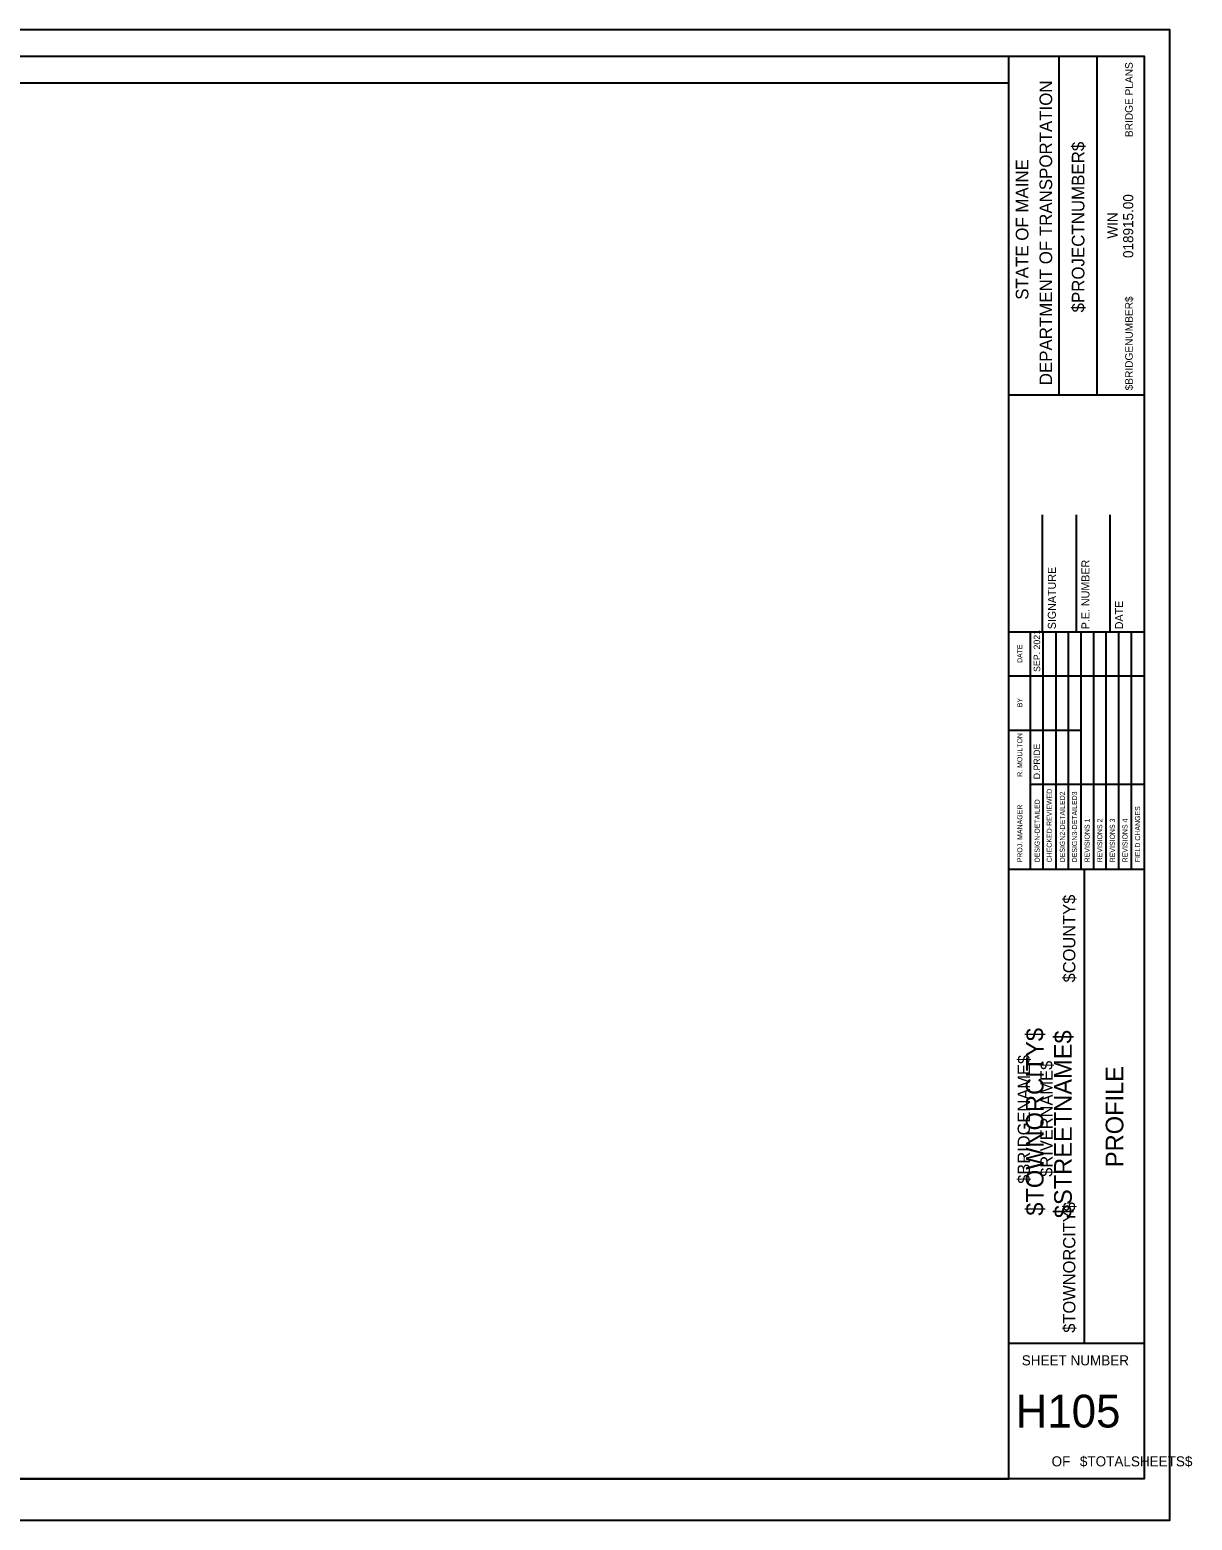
# Model space of a CAD drawing. Extents: x 36591 to 37449, y 9985 to 10535.
# Drawn here: x 37020 to 37449, y 9985 to 10535 of the extents above; entities that cross this region are included whole.
import ezdxf

# ---------------------------------------------------------------- set-up
doc = ezdxf.new("R2010")
doc.units = 0
for name, color, linetype in [('BORDER', 7, 'Continuous'), ('BRIDGE_TITLE', 7, 'Continuous'), ('CLIPS', 7, 'Continuous'), ('HIGHWAY_TITLE', 7, 'Continuous'), ('PLOT BOUNDARY', 7, 'Continuous')]:
    doc.layers.add(name, color=color, linetype=linetype)

msp = doc.modelspace()

# ---------------------------------------------------------------- linework, layer by layer
at = {"layer": 'BORDER'}
for p, q in [((37381.12, 10000), (37381.12, 10525)), ((37399.77, 10399.99), (37399.77, 10524.99)), ((37413.74, 10399.99), (37413.74, 10524.99)), ((37381.13, 10399.97), (37431.12, 10399.97)), ((37393.62, 10312.51), (37393.62, 10355.75)), ((37406.12, 10312.51), (37406.12, 10355.75)), ((37418.62, 10312.51), (37418.62, 10355.75)), ((37381.12, 10312.51), (37431.12, 10312.51)), ((37381.12, 10225.01), (37431.12, 10225.01)), ((37409.08, 10050.01), (37409.08, 10225.01)), ((37381.12, 10050.01), (37431.12, 10050.01))]:
    msp.add_line(p, q, dxfattribs=at)
msp.add_lwpolyline([(36631.12, 10525), (37431.12, 10525), (37431.12, 10000), (36631.12, 10000)], close=True, dxfattribs=at)
for points in [[(37389.2, 10296.26), (37389.2, 10312.51)], [(37393.86, 10225.03), (37393.86, 10312.51)], [(37398.52, 10312.51), (37398.52, 10225.03)], [(37403.18, 10225.03), (37403.18, 10312.51)], [(37407.84, 10225.03), (37407.84, 10312.51)], [(37412.5, 10225.03), (37412.5, 10312.51)], [(37417.15, 10225.03), (37417.15, 10312.51)], [(37421.81, 10225.03), (37421.81, 10312.51)], [(37426.47, 10225.03), (37426.47, 10312.51)], [(37389.2, 10225.03), (37389.2, 10308.98)], [(37381.12, 10296.26), (37431.12, 10296.26)], [(37381.12, 10276.26), (37389.2, 10276.26)], [(37389.2, 10276.26), (37407.83, 10276.26)], [(37389.2, 10256.26), (37431.12, 10256.26)]]:
    msp.add_lwpolyline(points, dxfattribs=at)
at = {"layer": 'CLIPS'}
msp.add_lwpolyline([(36631.12, 10000), (37381.12, 10000), (37381.12, 10515), (36631.12, 10515)], close=True, dxfattribs=at)
at = {"layer": 'PLOT BOUNDARY'}
msp.add_lwpolyline([(36590.66, 9984.7), (37440.66, 9984.7), (37440.66, 10534.7), (36590.66, 10534.7)], close=True, dxfattribs=at)

# ---------------------------------------------------------------- texts
at = {"layer": 'BORDER'}
for s, height, rotation, p in [('DEPARTMENT OF TRANSPORTATION', 4.6588, 90, (37397.16, 10403.53)), ('$PROJECTNUMBER$', 4.6588, 90, (37409.08, 10430.4)), ('STATE OF MAINE', 4.6588, 90, (37388.4, 10435.06)), ('018915.00', 3.726, 90, (37427.1, 10450.49)), ('WIN', 3.726, 90, (37421.31, 10457.65)), ('SIGNATURE', 2.953, 90, (37398.53, 10313.48)), ('P.E. NUMBER', 2.9528, 90, (37410.93, 10313.48)), ('DATE', 2.953, 90, (37423.33, 10313.48)), ('SEP. 2021', 2.423, 90, (37392.74, 10297.74)), ('DATE', 1.857, 90, (37386.15, 10301.04)), ('BY', 1.857, 90, (37386.15, 10284.69)), ('R. MOULTON', 1.864, 90, (37386.15, 10259.03)), ('D.PRIDE', 2.423, 90, (37392.74, 10258.13)), ('CHECKED-REVIEWED', 1.8637, 90, (37397.03, 10227.46)), ('DESIGN2-DETAILED2', 1.8637, 90, (37401.87, 10227.46)), ('DESIGN3-DETAILED3', 1.8637, 90, (37406.35, 10227.46)), ('PROJ. MANAGER', 1.8637, 90, (37386.15, 10227.46)), ('DESIGN-DETAILED', 1.8637, 90, (37392.56, 10227.46)), ('FIELD CHANGES', 1.8637, 90, (37429.64, 10227.46)), ('REVISIONS 1', 1.8637, 90, (37411, 10227.46)), ('REVISIONS 2', 1.8637, 90, (37415.66, 10227.46)), ('REVISIONS 3', 1.8637, 90, (37420.32, 10227.46)), ('REVISIONS 4', 1.8637, 90, (37424.98, 10227.46)), ('PROFILE', 6.521, 90, (37423.45, 10115)), ('SHEET NUMBER', 3.7264, 360, (37385.95, 10041.83)), ('H105', 12.097, 360, (37383.7, 10018.91)), ('OF', 3.726, 360, (37396.96, 10004.56)), ('$TOTALSHEETS$', 3.7264, 360, (37407.41, 10004.56))]:
    msp.add_text(s, height=height, rotation=rotation, dxfattribs=at).set_placement(p)
at = {"layer": 'BRIDGE_TITLE'}
for s, height, p in [('BRIDGE PLANS', 2.795, (37426.92, 10495.12)), ('$BRIDGENUMBER$', 2.795, (37426.92, 10401.65)), ('$COUNTY$', 4.536, (37405.73, 10183.17)), ('$BRIDGENAME$', 4.5358, (37388.96, 10108.86)), ('$RIVERNAME$', 4.5358, (37397.34, 10111.43)), ('$TOWNORCITY$', 4.5358, (37405.73, 10053.88))]:
    msp.add_text(s, height=height, rotation=90, dxfattribs=at).set_placement(p)
at = {"layer": 'HIGHWAY_TITLE'}
for s, p in [('$TOWNORCITY$', (37393.99, 10097.06)), ('$STREETNAME$', (37404.42, 10096.16))]:
    msp.add_text(s, height=6.5214, rotation=90, dxfattribs=at).set_placement(p)

doc.saveas('drawing.dxf')
